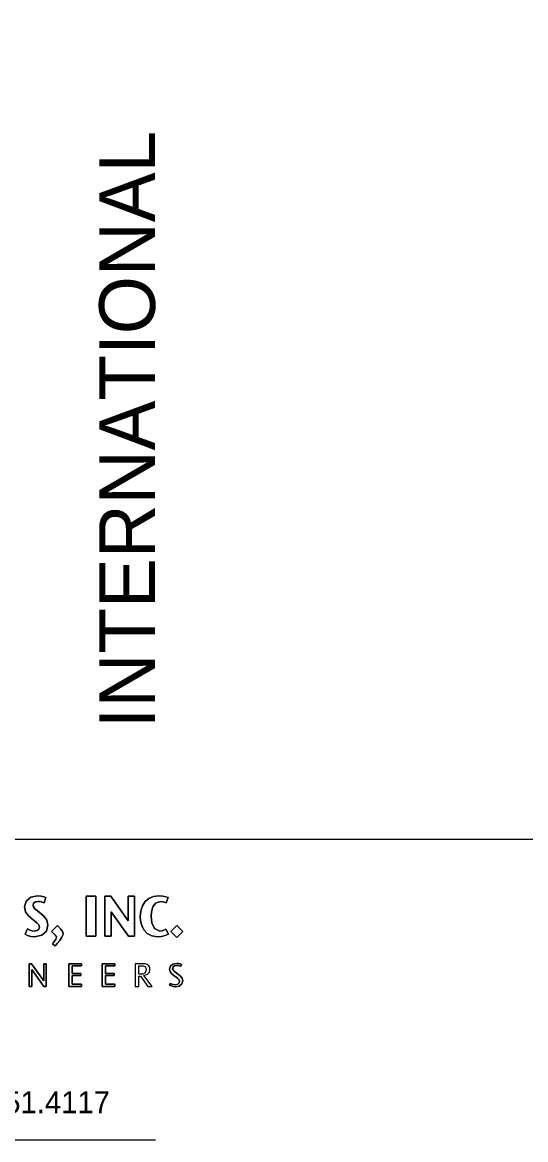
# Model space of a CAD drawing. Extents: x 0.3 to 16.7, y 0.2 to 10.7.
# Drawn here: x 2.512 to 3.639, y 0.319 to 2.82 of the extents above; entities that cross this region are included whole.
import ezdxf

# ---------------------------------------------------------------- set-up
doc = ezdxf.new("R2010")
doc.units = 0
for name, color, linetype in [('63-KAPUR-LOGO', 7, 'Continuous'), ('P_Impacts_Assumed', 7, 'Continuous'), ('PLT_Sheet_Info', 7, 'Continuous')]:
    doc.layers.add(name, color=color, linetype=linetype)

msp = doc.modelspace()

# ---------------------------------------------------------------- linework, layer by layer
at = {"layer": '63-KAPUR-LOGO'}
for p, q in [((2.5165, 0.8401), (2.5203, 0.8529)), ((2.5203, 0.8529), (2.5306, 0.8619)), ((2.5306, 0.8619), (2.546, 0.8652)), ((2.541, 0.8513), (2.5371, 0.8483)), ((2.5471, 0.8524), (2.541, 0.8513)), ((2.546, 0.8652), (2.5538, 0.8646)), ((2.5516, 0.852), (2.5471, 0.8524)), ((2.5559, 0.851), (2.5516, 0.852)), ((2.5538, 0.8646), (2.5601, 0.8631)), ((2.5604, 0.8493), (2.5559, 0.851)), ((2.5601, 0.8631), (2.5648, 0.8614)), ((2.5648, 0.8614), (2.5604, 0.8493)), ((2.655, 0.7745), (2.655, 0.8639)), ((2.655, 0.8639), (2.6767, 0.8639)), ((2.6767, 0.8639), (2.6767, 0.7745)), ((2.6963, 0.7745), (2.6963, 0.8639)), ((2.6963, 0.8639), (2.71, 0.8639)), ((2.71, 0.8639), (2.7487, 0.8093)), ((2.7487, 0.8093), (2.7487, 0.8639)), ((2.7487, 0.8639), (2.7634, 0.8639)), ((2.7634, 0.8639), (2.7634, 0.7745)), ((2.7809, 0.8429), (2.7869, 0.8522)), ((2.7869, 0.8522), (2.7951, 0.8592)), ((2.7951, 0.8592), (2.8054, 0.8637)), ((2.8054, 0.8637), (2.8175, 0.8653)), ((2.8209, 0.8524), (2.8104, 0.8488)), ((2.8175, 0.8653), (2.8264, 0.8646)), ((2.8259, 0.8518), (2.8209, 0.8524)), ((2.8303, 0.8506), (2.8259, 0.8518)), ((2.8264, 0.8646), (2.8334, 0.863)), ((2.8337, 0.8491), (2.8303, 0.8506)), ((2.8334, 0.863), (2.8386, 0.861)), ((2.8386, 0.861), (2.8337, 0.8491)), ((2.5188, 0.8294), (2.5165, 0.8401)), ((2.5253, 0.8204), (2.5188, 0.8294)), ((2.5371, 0.8483), (2.5358, 0.8439)), ((2.5358, 0.8439), (2.5367, 0.84)), ((2.5367, 0.84), (2.5399, 0.836)), ((2.5399, 0.836), (2.5456, 0.8312)), ((2.5456, 0.8312), (2.5501, 0.8278)), ((2.5501, 0.8278), (2.56, 0.8197)), ((2.7498, 0.7745), (2.7111, 0.8292)), ((2.7111, 0.8292), (2.7111, 0.7745)), ((2.7759, 0.819), (2.7772, 0.8317)), ((2.7772, 0.8317), (2.7809, 0.8429)), ((2.8011, 0.8292), (2.8003, 0.8195)), ((2.8041, 0.84), (2.8011, 0.8292)), ((2.8104, 0.8488), (2.8041, 0.84)), ((2.535, 0.8121), (2.5253, 0.8204)), ((2.5392, 0.8088), (2.535, 0.8121)), ((2.5452, 0.8039), (2.5392, 0.8088)), ((2.5488, 0.7997), (2.5452, 0.8039)), ((2.56, 0.8197), (2.5668, 0.8108)), ((2.5668, 0.8108), (2.5693, 0.7994)), ((2.7767, 0.8087), (2.7759, 0.819)), ((2.7793, 0.7983), (2.7767, 0.8087)), ((2.8003, 0.8195), (2.802, 0.8047)), ((2.802, 0.8047), (2.8079, 0.7917)), ((2.5179, 0.779), (2.5233, 0.7908)), ((2.5237, 0.7763), (2.5179, 0.779)), ((2.5233, 0.7908), (2.5283, 0.7884)), ((2.5309, 0.7741), (2.5237, 0.7763)), ((2.5283, 0.7884), (2.5336, 0.7867)), ((2.5336, 0.7867), (2.5392, 0.786)), ((2.5392, 0.786), (2.5454, 0.7874)), ((2.5558, 0.7768), (2.5399, 0.7732)), ((2.5454, 0.7874), (2.5489, 0.7907)), ((2.55, 0.795), (2.5488, 0.7997)), ((2.5489, 0.7907), (2.55, 0.795)), ((2.5659, 0.7862), (2.5558, 0.7768)), ((2.5693, 0.7994), (2.5659, 0.7862)), ((2.577, 0.7852), (2.5905, 0.7987)), ((2.5842, 0.7784), (2.577, 0.7852)), ((2.5873, 0.7747), (2.5842, 0.7784)), ((2.5905, 0.7987), (2.5983, 0.7905)), ((2.5983, 0.7905), (2.602, 0.7852)), ((2.6026, 0.7768), (2.6006, 0.7721)), ((2.602, 0.7852), (2.603, 0.7801)), ((2.603, 0.7801), (2.6026, 0.7768)), ((2.7841, 0.7887), (2.7793, 0.7983)), ((2.7914, 0.7806), (2.7841, 0.7887)), ((2.8016, 0.7752), (2.7914, 0.7806)), ((2.8079, 0.7917), (2.8195, 0.7861)), ((2.8195, 0.7861), (2.8253, 0.7868)), ((2.8316, 0.7759), (2.8237, 0.7739)), ((2.8253, 0.7868), (2.8301, 0.7886)), ((2.8301, 0.7886), (2.8335, 0.7904)), ((2.8389, 0.7789), (2.8316, 0.7759)), ((2.8335, 0.7904), (2.8389, 0.7789)), ((2.8445, 0.7853), (2.858, 0.7989)), ((2.858, 0.7718), (2.8445, 0.7853)), ((2.858, 0.7989), (2.8716, 0.7853)), ((2.8716, 0.7853), (2.858, 0.7718)), ((2.5399, 0.7732), (2.5309, 0.7741)), ((2.5793, 0.7579), (2.5836, 0.7635)), ((2.5849, 0.7528), (2.5793, 0.7579)), ((2.5836, 0.7635), (2.5867, 0.7683)), ((2.5866, 0.7548), (2.5849, 0.7528)), ((2.5896, 0.7583), (2.5866, 0.7548)), ((2.5867, 0.7683), (2.588, 0.772)), ((2.588, 0.772), (2.5873, 0.7747)), ((2.5955, 0.765), (2.5896, 0.7583)), ((2.6006, 0.7721), (2.5955, 0.765)), ((2.6767, 0.7745), (2.655, 0.7745)), ((2.7111, 0.7745), (2.6963, 0.7745)), ((2.7634, 0.7745), (2.7498, 0.7745)), ((2.8149, 0.7732), (2.8016, 0.7752)), ((2.8237, 0.7739), (2.8149, 0.7732)), ((2.5275, 0.6621), (2.5275, 0.7131)), ((2.5275, 0.7131), (2.5327, 0.7131)), ((2.5327, 0.7131), (2.5597, 0.675)), ((2.5597, 0.675), (2.5597, 0.7131)), ((2.5597, 0.7131), (2.5653, 0.7131)), ((2.5653, 0.7131), (2.5653, 0.6621)), ((2.6157, 0.6621), (2.6157, 0.7131)), ((2.6157, 0.7131), (2.6443, 0.7131)), ((2.6443, 0.7084), (2.6238, 0.7084)), ((2.6238, 0.7084), (2.6238, 0.6908)), ((2.6443, 0.7131), (2.6443, 0.7084)), ((2.6903, 0.6621), (2.6903, 0.7131)), ((2.6903, 0.7131), (2.7188, 0.7131)), ((2.7188, 0.7084), (2.6983, 0.7084)), ((2.6983, 0.7084), (2.6983, 0.6908)), ((2.7188, 0.7131), (2.7188, 0.7084)), ((2.7649, 0.7131), (2.7649, 0.6621)), ((2.7777, 0.7131), (2.7649, 0.7131)), ((2.7729, 0.6894), (2.7729, 0.7086)), ((2.7729, 0.7086), (2.777, 0.7086)), ((2.777, 0.7086), (2.7827, 0.7083)), ((2.7829, 0.713), (2.7777, 0.7131)), ((2.7827, 0.7083), (2.7875, 0.706)), ((2.7873, 0.7125), (2.7829, 0.713)), ((2.7913, 0.7111), (2.7873, 0.7125)), ((2.7875, 0.706), (2.7894, 0.6997)), ((2.7949, 0.7082), (2.7913, 0.7111)), ((2.7971, 0.7046), (2.7949, 0.7082)), ((2.7963, 0.6944), (2.7977, 0.7006)), ((2.7977, 0.7006), (2.7971, 0.7046)), ((2.8412, 0.7009), (2.8434, 0.7076)), ((2.8427, 0.695), (2.8412, 0.7009)), ((2.8434, 0.7076), (2.8491, 0.7121)), ((2.8497, 0.7058), (2.8486, 0.7023)), ((2.8486, 0.7023), (2.8493, 0.6995)), ((2.8491, 0.7121), (2.8575, 0.7138)), ((2.8529, 0.7082), (2.8497, 0.7058)), ((2.8577, 0.7091), (2.8529, 0.7082)), ((2.8575, 0.7138), (2.8614, 0.7135)), ((2.8605, 0.7089), (2.8577, 0.7091)), ((2.8636, 0.7082), (2.8605, 0.7089)), ((2.8614, 0.7135), (2.865, 0.7128)), ((2.8667, 0.7072), (2.8636, 0.7082)), ((2.865, 0.7128), (2.8683, 0.7116)), ((2.8683, 0.7116), (2.8667, 0.7072)), ((2.5601, 0.6621), (2.5331, 0.7002)), ((2.5331, 0.7002), (2.5331, 0.6621)), ((2.6238, 0.6908), (2.6429, 0.6908)), ((2.6429, 0.6863), (2.6238, 0.6863)), ((2.6238, 0.6863), (2.6238, 0.6671)), ((2.6429, 0.6908), (2.6429, 0.6863)), ((2.6983, 0.6908), (2.7175, 0.6908)), ((2.7175, 0.6863), (2.6983, 0.6863)), ((2.6983, 0.6863), (2.6983, 0.6671)), ((2.7175, 0.6908), (2.7175, 0.6863)), ((2.7764, 0.6894), (2.7729, 0.6894)), ((2.7729, 0.6621), (2.7729, 0.6853)), ((2.7729, 0.6853), (2.7767, 0.6853)), ((2.7818, 0.6897), (2.7764, 0.6894)), ((2.7767, 0.6853), (2.7928, 0.6621)), ((2.7871, 0.6924), (2.7818, 0.6897)), ((2.7842, 0.6865), (2.7918, 0.6895)), ((2.8024, 0.6621), (2.7842, 0.6865)), ((2.7894, 0.6997), (2.7871, 0.6924)), ((2.7918, 0.6895), (2.7963, 0.6944)), ((2.8466, 0.6903), (2.8427, 0.695)), ((2.8521, 0.686), (2.8466, 0.6903)), ((2.8493, 0.6995), (2.8516, 0.6965)), ((2.8516, 0.6965), (2.856, 0.693)), ((2.8553, 0.6835), (2.8521, 0.686)), ((2.8601, 0.6799), (2.8553, 0.6835)), ((2.856, 0.693), (2.8593, 0.6906)), ((2.8593, 0.6906), (2.8656, 0.6858)), ((2.8629, 0.6767), (2.8601, 0.6799)), ((2.8638, 0.6733), (2.8629, 0.6767)), ((2.8656, 0.6858), (2.8697, 0.681)), ((2.8697, 0.681), (2.8712, 0.675)), ((2.5331, 0.6621), (2.5275, 0.6621)), ((2.5653, 0.6621), (2.5601, 0.6621)), ((2.6446, 0.6621), (2.6157, 0.6621)), ((2.6238, 0.6671), (2.6446, 0.6671)), ((2.6446, 0.6671), (2.6446, 0.6621)), ((2.7192, 0.6621), (2.6903, 0.6621)), ((2.6983, 0.6671), (2.7192, 0.6671)), ((2.7192, 0.6671), (2.7192, 0.6621)), ((2.7649, 0.6621), (2.7729, 0.6621)), ((2.7928, 0.6621), (2.8024, 0.6621)), ((2.8415, 0.6648), (2.8436, 0.6691)), ((2.845, 0.6632), (2.8415, 0.6648)), ((2.8436, 0.6691), (2.8468, 0.6676)), ((2.8494, 0.6619), (2.845, 0.6632)), ((2.8468, 0.6676), (2.8505, 0.6665)), ((2.8548, 0.6613), (2.8494, 0.6619)), ((2.8505, 0.6665), (2.8547, 0.666)), ((2.8547, 0.666), (2.8599, 0.6671)), ((2.8634, 0.6631), (2.8548, 0.6613)), ((2.8599, 0.6671), (2.8629, 0.6699)), ((2.8629, 0.6699), (2.8638, 0.6733)), ((2.8691, 0.668), (2.8634, 0.6631)), ((2.8712, 0.675), (2.8691, 0.668)), ((1.4328, 0.3192), (2.8104, 0.3192))]:
    msp.add_line(p, q, dxfattribs=at)
for points in [[(2.5203, 0.8529), (2.5165, 0.8401), (2.5188, 0.8294), (2.5253, 0.8204), (2.535, 0.8121), (2.5392, 0.8088), (2.5452, 0.8039), (2.5488, 0.7997), (2.55, 0.795), (2.5489, 0.7907), (2.5454, 0.7874), (2.5392, 0.786), (2.5336, 0.7867), (2.5283, 0.7884), (2.5233, 0.7908), (2.5179, 0.779), (2.5237, 0.7763), (2.5309, 0.7741), (2.5399, 0.7732), (2.5558, 0.7768), (2.5659, 0.7862), (2.5693, 0.7994), (2.5668, 0.8108), (2.56, 0.8197), (2.5501, 0.8278), (2.5456, 0.8312), (2.5399, 0.836), (2.5367, 0.84), (2.5358, 0.8439), (2.5371, 0.8483), (2.541, 0.8513), (2.5471, 0.8524), (2.5516, 0.852), (2.5559, 0.851), (2.5604, 0.8493), (2.5648, 0.8614), (2.5601, 0.8631), (2.5538, 0.8646), (2.546, 0.8652), (2.5306, 0.8619), (2.5203, 0.8529)], [(2.655, 0.7745), (2.6767, 0.7745), (2.6767, 0.8639), (2.655, 0.8639), (2.655, 0.7745)], [(2.7111, 0.8292), (2.7498, 0.7745), (2.7634, 0.7745), (2.7634, 0.8639), (2.7487, 0.8639), (2.7487, 0.8093), (2.71, 0.8639), (2.6963, 0.8639), (2.6963, 0.7745), (2.7111, 0.7745), (2.7111, 0.8292)], [(2.7759, 0.819), (2.7767, 0.8087), (2.7793, 0.7983), (2.7841, 0.7887), (2.7914, 0.7806), (2.8016, 0.7752), (2.8149, 0.7732), (2.8237, 0.7739), (2.8316, 0.7759), (2.8389, 0.7789), (2.8335, 0.7904), (2.8301, 0.7886), (2.8253, 0.7868), (2.8195, 0.7861), (2.8079, 0.7917), (2.802, 0.8047), (2.8003, 0.8195), (2.8011, 0.8292), (2.8041, 0.84), (2.8104, 0.8488), (2.8209, 0.8524), (2.8259, 0.8518), (2.8303, 0.8506), (2.8337, 0.8491), (2.8386, 0.861), (2.8334, 0.863), (2.8264, 0.8646), (2.8175, 0.8653), (2.8054, 0.8637), (2.7951, 0.8592), (2.7869, 0.8522), (2.7809, 0.8429), (2.7772, 0.8317), (2.7759, 0.819)], [(2.5983, 0.7905), (2.5905, 0.7987), (2.577, 0.7852), (2.5842, 0.7784), (2.5884, 0.7733), (2.5867, 0.7683), (2.5836, 0.7635), (2.5793, 0.7579), (2.5849, 0.7528), (2.5866, 0.7548), (2.5896, 0.7583), (2.5955, 0.765), (2.6006, 0.7721), (2.6026, 0.7768), (2.603, 0.7801), (2.602, 0.7852), (2.5983, 0.7905)], [(2.858, 0.7718), (2.8716, 0.7853), (2.858, 0.7989), (2.8445, 0.7853), (2.858, 0.7718)], [(2.5275, 0.6621), (2.5331, 0.6621), (2.5331, 0.7002), (2.5601, 0.6621), (2.5653, 0.6621), (2.5653, 0.7131), (2.5597, 0.7131), (2.5597, 0.675), (2.5327, 0.7131), (2.5275, 0.7131), (2.5275, 0.6621)], [(2.6157, 0.7131), (2.6157, 0.6621), (2.6446, 0.6621), (2.6446, 0.6671), (2.6238, 0.6671), (2.6238, 0.6863), (2.6429, 0.6863), (2.6429, 0.6908), (2.6238, 0.6908), (2.6238, 0.7084), (2.6443, 0.7084), (2.6443, 0.7131), (2.6157, 0.7131)], [(2.6983, 0.7084), (2.7188, 0.7084), (2.7188, 0.7131), (2.6903, 0.7131), (2.6903, 0.6621), (2.7192, 0.6621), (2.7192, 0.6671), (2.6983, 0.6671), (2.6983, 0.6863), (2.7175, 0.6863), (2.7175, 0.6908), (2.6983, 0.6908), (2.6983, 0.7084)], [(2.7649, 0.6621), (2.7729, 0.6621), (2.7729, 0.6853), (2.7767, 0.6853), (2.7928, 0.6621), (2.8024, 0.6621), (2.7842, 0.6865), (2.7918, 0.6895), (2.7963, 0.6944), (2.7977, 0.7006), (2.7971, 0.7046), (2.7949, 0.7082), (2.7913, 0.7111), (2.7873, 0.7125), (2.7829, 0.713), (2.7777, 0.7131), (2.7649, 0.7131), (2.7649, 0.6621)], [(2.7729, 0.7086), (2.777, 0.7086), (2.7827, 0.7083), (2.7875, 0.706), (2.7894, 0.6997), (2.7871, 0.6924), (2.7818, 0.6897), (2.7764, 0.6894), (2.7729, 0.6894), (2.7729, 0.7086)], [(2.8497, 0.7058), (2.8529, 0.7082), (2.8587, 0.7093), (2.8636, 0.7082), (2.8667, 0.7072), (2.8683, 0.7116), (2.865, 0.7128), (2.8614, 0.7135), (2.8575, 0.7138), (2.8491, 0.7121), (2.8434, 0.7076), (2.8412, 0.7009), (2.8427, 0.695), (2.8466, 0.6903), (2.8521, 0.686), (2.8553, 0.6835), (2.8601, 0.6799), (2.8629, 0.6767), (2.8638, 0.6733), (2.8629, 0.6699), (2.8599, 0.6671), (2.8547, 0.666), (2.8505, 0.6665), (2.8468, 0.6676), (2.8436, 0.6691), (2.8415, 0.6648), (2.845, 0.6632), (2.8494, 0.6619), (2.8548, 0.6613), (2.8634, 0.6631), (2.8691, 0.668), (2.8712, 0.675), (2.8697, 0.681), (2.8656, 0.6858), (2.8593, 0.6906), (2.856, 0.693), (2.8516, 0.6965), (2.8482, 0.7009), (2.8497, 0.7058)]]:
    msp.add_lwpolyline(points, dxfattribs=at)
at = {"layer": 'P_Impacts_Assumed'}
msp.add_lwpolyline([(0.3456, 5.8545), (16.742, 5.8545), (16.742, 0.9907), (0.3456, 0.9907)], close=True, dxfattribs=at)

# ---------------------------------------------------------------- texts
at = {"layer": '63-KAPUR-LOGO'}
msp.add_text('Phone: 414.351.6668         Fax: 414.351.4117', height=0.04898, dxfattribs=at).set_placement((1.3716, 0.3785))
at = {"layer": 'PLT_Sheet_Info'}
msp.add_text('INTERNATIONAL ', height=0.125, rotation=90, dxfattribs=at).set_placement((2.809, 1.2398))

doc.saveas('drawing.dxf')
